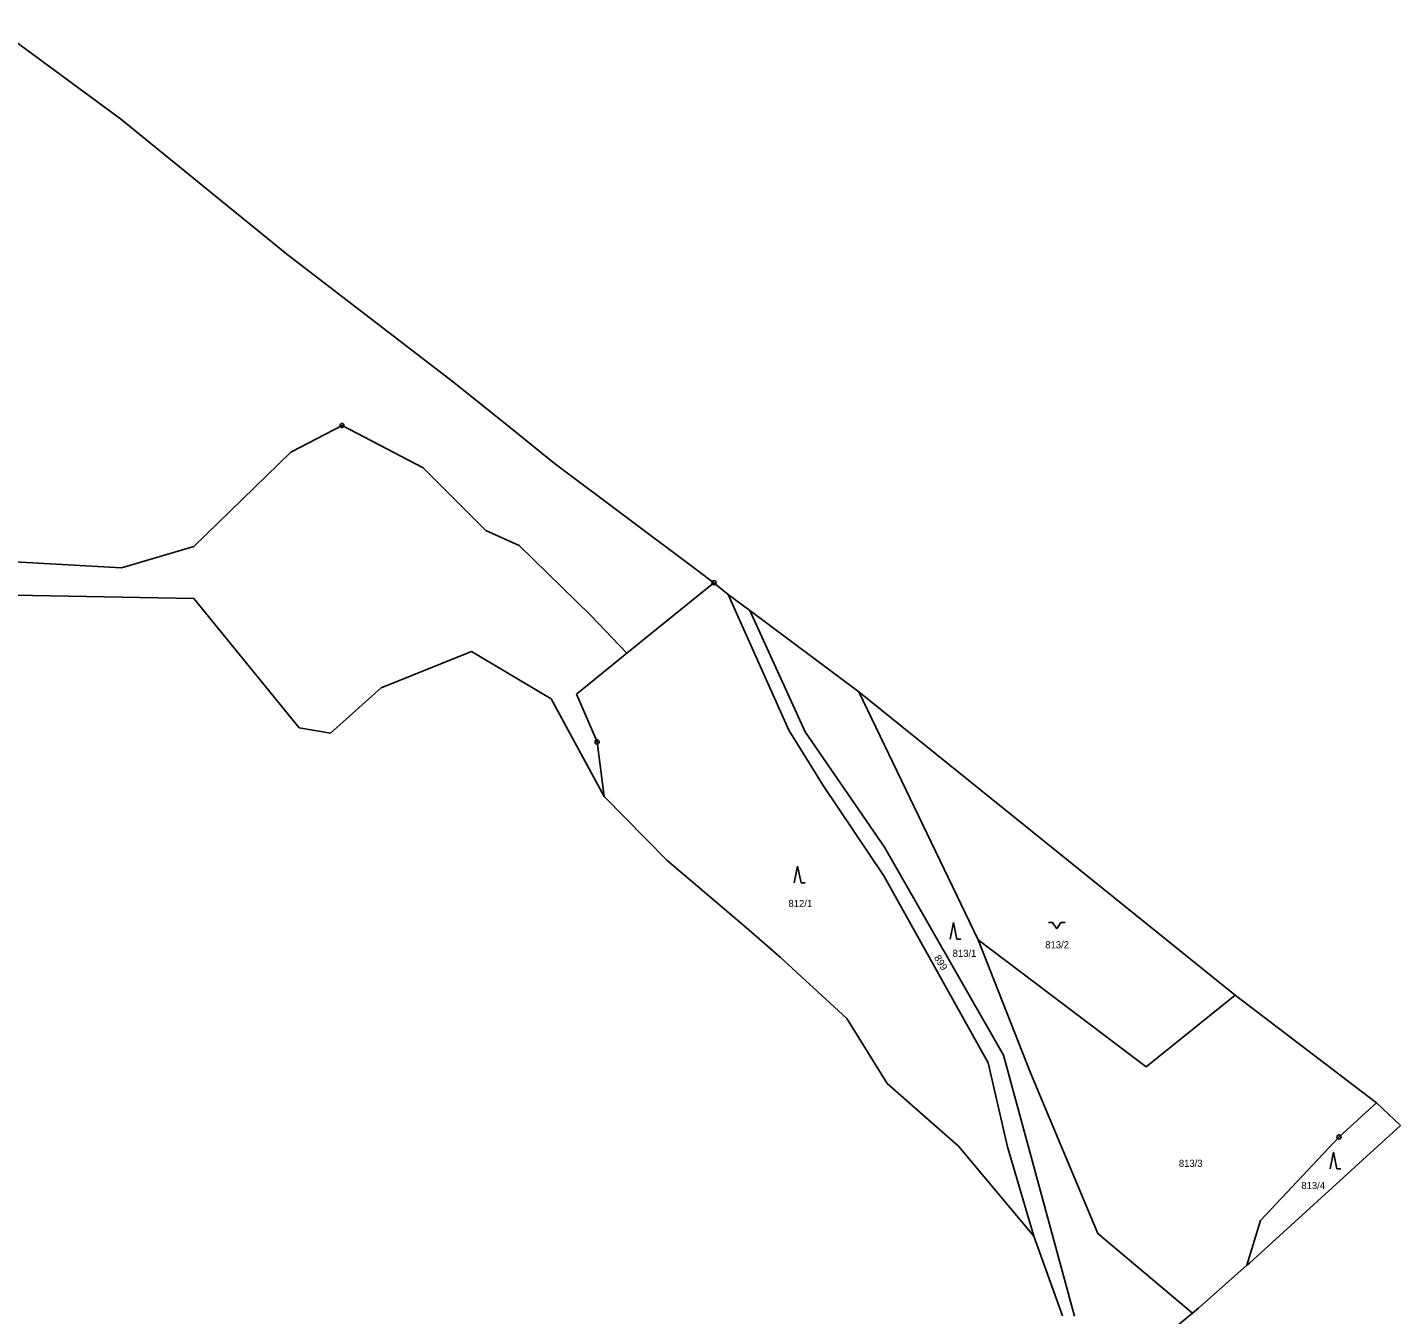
# Model space of a CAD drawing. Extents: x -796130 to -793145, y -1109506 to -1106267.
# Drawn here: x -793563.6 to -793234.4, y -1108894.6 to -1108586.2 of the extents above; entities that cross this region are included whole.
import ezdxf

# ---------------------------------------------------------------- set-up
doc = ezdxf.new("R2010")
doc.units = 0
for name, color, linetype in [('Vrstva 1', 7, 'Continuous'), ('Vrstva 14', 7, 'Continuous'), ('Vrstva 23', 7, 'Continuous'), ('Vrstva 28', 7, 'Continuous'), ('Vrstva 4', 7, 'Continuous')]:
    doc.layers.add(name, color=color, linetype=linetype)

msp = doc.modelspace()

# ---------------------------------------------------------------- linework, layer by layer
at = {"layer": 'Vrstva 1'}
for p, q in [((-793500.46, -1108687.99), (-793488.18, -1108681.6)), ((-793488.18, -1108681.6), (-793468.75, -1108691.72)), ((-793523.71, -1108710.56), (-793500.46, -1108687.99)), ((-793468.75, -1108691.72), (-793453.68, -1108706.75)), ((-793453.68, -1108706.75), (-793445.68, -1108710.31)), ((-793541.02, -1108715.73), (-793523.71, -1108710.56)), ((-793445.68, -1108710.31), (-793428.64, -1108727.06)), ((-793598.38, -1108712.45), (-793541.02, -1108715.73)), ((-793523.72, -1108723.05), (-793650.29, -1108720.72)), ((-793399.02, -1108719.27), (-793419.9, -1108736.12)), ((-793381.1, -1108754.56), (-793395.58, -1108722.07)), ((-793498.42, -1108754.02), (-793523.72, -1108723.05)), ((-793428.64, -1108727.06), (-793419.9, -1108736.12)), ((-793390.43, -1108725.91), (-793377.14, -1108755.02)), ((-793457.12, -1108735.72), (-793478.82, -1108744.47)), ((-793438.01, -1108747.06), (-793457.12, -1108735.72)), ((-793419.9, -1108736.12), (-793431.99, -1108745.97)), ((-793478.82, -1108744.47), (-793490.97, -1108755.32)), ((-793425.3, -1108770.47), (-793438.01, -1108747.06)), ((-793431.99, -1108745.97), (-793427.03, -1108757.41)), ((-793335.67, -1108804.82), (-793364.25, -1108745.42)), ((-793490.97, -1108755.32), (-793498.42, -1108754.02)), ((-793372.83, -1108767.82), (-793381.1, -1108754.56)), ((-793427.03, -1108757.41), (-793425.3, -1108770.47)), ((-793377.14, -1108755.02), (-793358.15, -1108782.6)), ((-793358.27, -1108789.5), (-793372.83, -1108767.82)), ((-793425.3, -1108770.47), (-793410.33, -1108785.75)), ((-793358.15, -1108782.6), (-793329.58, -1108832.49)), ((-793410.33, -1108785.75), (-793391.2, -1108801.96)), ((-793333.32, -1108834.34), (-793358.27, -1108789.5)), ((-793391.2, -1108801.96), (-793383.15, -1108808.95)), ((-793323.15, -1108836.7), (-793335.67, -1108804.82)), ((-793335.67, -1108804.82), (-793295.43, -1108835.26)), ((-793383.15, -1108808.95), (-793367.2, -1108823.71)), ((-793274.09, -1108818.1), (-793295.43, -1108835.26)), ((-793367.2, -1108823.71), (-793357.5, -1108839.25)), ((-793312.55, -1108895.04), (-793329.58, -1108832.49)), ((-793328.65, -1108854.42), (-793333.32, -1108834.34)), ((-793306.98, -1108875.2), (-793323.15, -1108836.7)), ((-793357.5, -1108839.25), (-793340.36, -1108854.3)), ((-793240.16, -1108843.88), (-793249.18, -1108852.06)), ((-793249.18, -1108852.06), (-793268, -1108872.12)), ((-793340.36, -1108854.3), (-793322.3, -1108875.82)), ((-793322.3, -1108875.82), (-793328.65, -1108854.42)), ((-793271.25, -1108882.8), (-793268, -1108872.12)), ((-793322.3, -1108875.82), (-793315.43, -1108894.92)), ((-793284.27, -1108894.3), (-793306.98, -1108875.2))]:
    msp.add_line(p, q, dxfattribs=at)
at = {"layer": 'Vrstva 23'}
for p, q in [((-793379.75, -1108791.2), (-793378.95, -1108787.2)), ((-793378.95, -1108787.2), (-793378.15, -1108791.2)), ((-793378.15, -1108791.2), (-793377.15, -1108791.2)), ((-793342.41, -1108804.65), (-793341.61, -1108800.65)), ((-793341.61, -1108800.65), (-793340.81, -1108804.65)), ((-793318.85, -1108800.69), (-793317.85, -1108800.69)), ((-793317.85, -1108800.69), (-793316.85, -1108802.19)), ((-793316.85, -1108802.19), (-793315.85, -1108800.69)), ((-793315.85, -1108800.69), (-793314.85, -1108800.69)), ((-793340.81, -1108804.65), (-793339.81, -1108804.65)), ((-793251.32, -1108859.74), (-793250.52, -1108855.74)), ((-793250.52, -1108855.74), (-793249.72, -1108859.74)), ((-793249.72, -1108859.74), (-793248.72, -1108859.74))]:
    msp.add_line(p, q, dxfattribs=at)
at = {"layer": 'Vrstva 28'}
for centre, radius in [((-793488.18, -1108681.6), 0.5), ((-793488.18, -1108681.6), 0.01), ((-793399.02, -1108719.27), 0.5), ((-793399.02, -1108719.27), 0.01), ((-793427.03, -1108757.41), 0.5), ((-793427.03, -1108757.41), 0.01), ((-793249.18, -1108852.06), 0.5), ((-793249.18, -1108852.06), 0.01)]:
    msp.add_circle(centre, radius, dxfattribs=at)
at = {"layer": 'Vrstva 4'}
for p, q in [((-793541.27, -1108608.11), (-793571.03, -1108586.23)), ((-793523.72, -1108622.44), (-793541.27, -1108608.11)), ((-793501.4, -1108640.55), (-793523.72, -1108622.44)), ((-793461.44, -1108671.2), (-793501.4, -1108640.55)), ((-793447.8, -1108682.17), (-793461.44, -1108671.2)), ((-793437.3, -1108690.61), (-793447.8, -1108682.17)), ((-793402.64, -1108716.56), (-793437.3, -1108690.61)), ((-793399.02, -1108719.27), (-793402.64, -1108716.56)), ((-793399.02, -1108719.27), (-793395.58, -1108722.07)), ((-793395.58, -1108722.07), (-793390.43, -1108725.91)), ((-793390.43, -1108725.91), (-793364.25, -1108745.42)), ((-793364.25, -1108745.42), (-793274.09, -1108818.1)), ((-793274.09, -1108818.1), (-793240.16, -1108843.88)), ((-793240.16, -1108843.88), (-793234.43, -1108849.34)), ((-793234.43, -1108849.34), (-793270.67, -1108882.27)), ((-793271.25, -1108882.8), (-793282.9, -1108893.09)), ((-793270.67, -1108882.27), (-793271.25, -1108882.8)), ((-793282.9, -1108893.09), (-793284.27, -1108894.3)), ((-793284.27, -1108894.3), (-793312.56, -1108917.24))]:
    msp.add_line(p, q, dxfattribs=at)

# ---------------------------------------------------------------- texts
at = {"layer": 'Vrstva 14'}
for s, p in [('812/1', (-793381.15, -1108796.97)), ('813/1', (-793341.8, -1108808.92)), ('813/2', (-793319.6, -1108806.86)), ('813/3', (-793287.57, -1108859.23)), ('813/4', (-793258.21, -1108864.55))]:
    msp.add_text(s, height=1.7, dxfattribs=at).set_placement(p)
msp.add_text('899', height=1.7, rotation=301.27932, dxfattribs=at).set_placement((-793346.33, -1108809.11))

doc.saveas('drawing.dxf')
